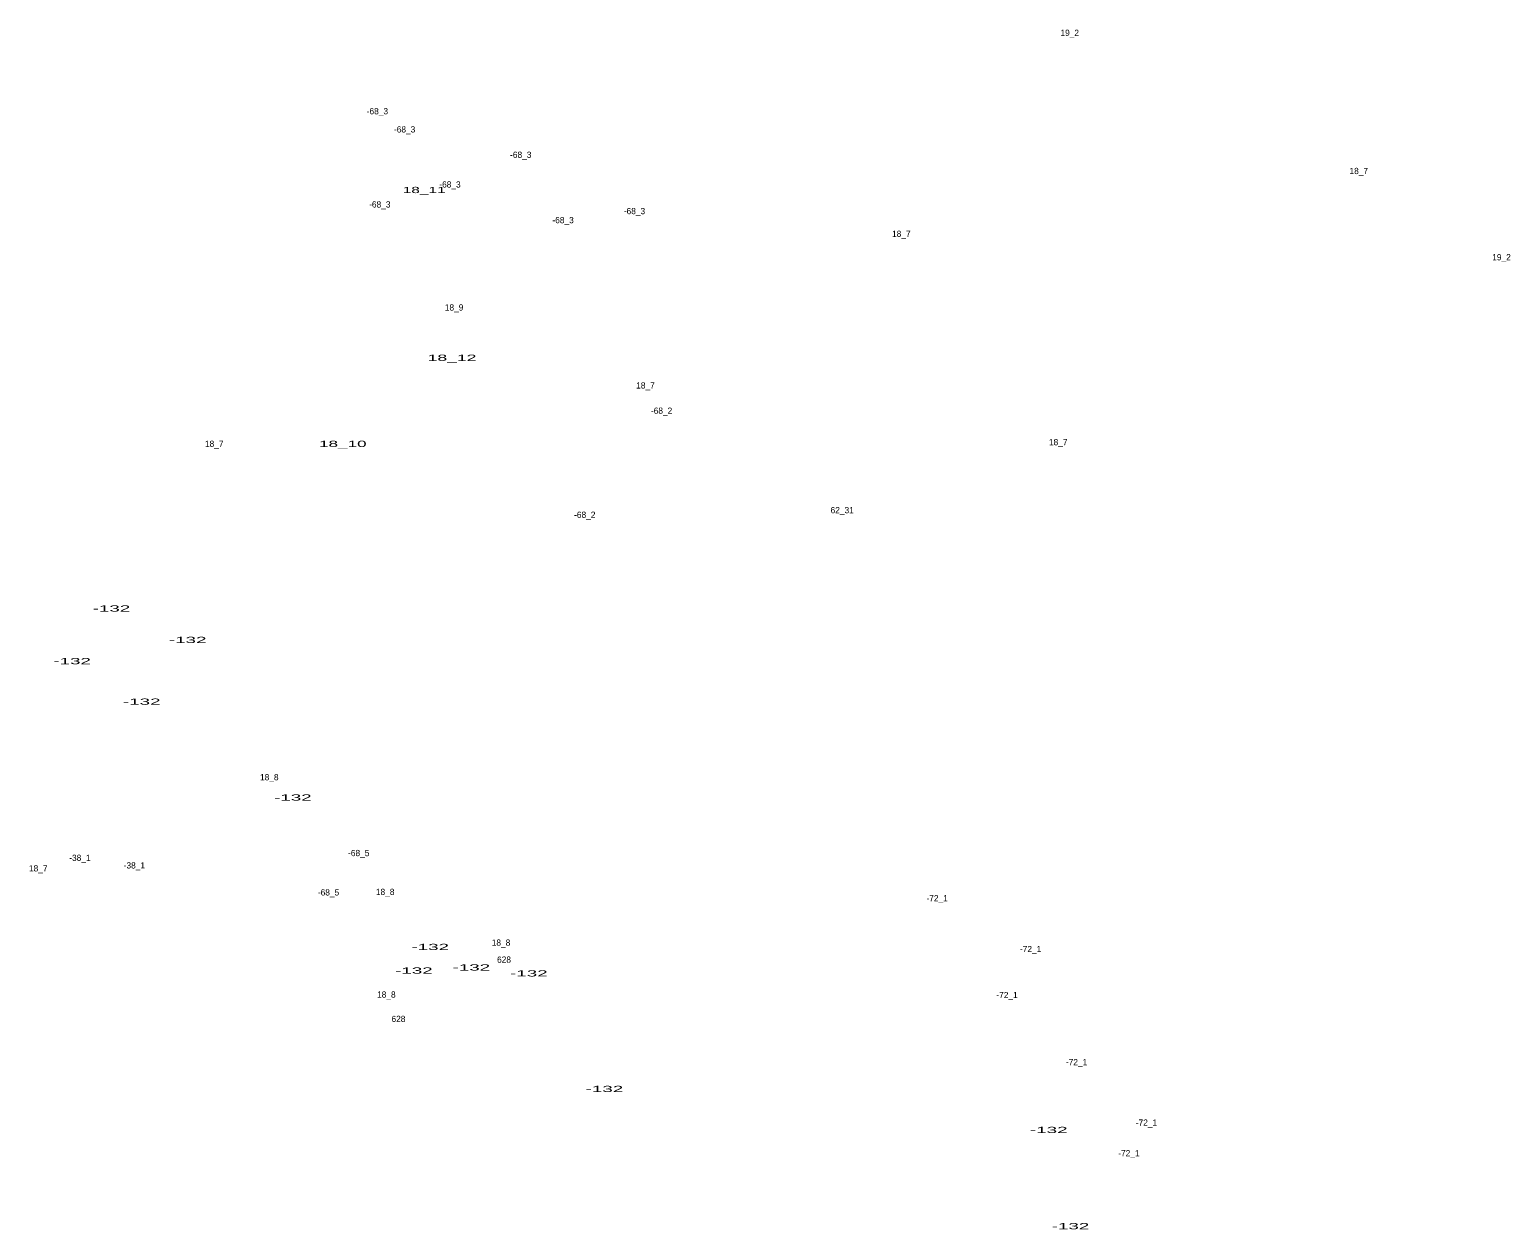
# Model space of a CAD drawing. Extents: x -661742 to -657295, y -1002932 to -996888.
# Drawn here: x -660423 to -659474, y -1002932 to -1002163 of the extents above; entities that cross this region are included whole.
import ezdxf
from ezdxf.enums import TextEntityAlignment as Align

# ---------------------------------------------------------------- set-up
doc = ezdxf.new("R2010")
doc.units = 0
doc.header["$LTSCALE"] = 1.6
doc.layers.add('24', color=7, linetype='Continuous')

msp = doc.modelspace()

# ---------------------------------------------------------------- texts
at = {"layer": '24'}
for s, p in [('19_2', (-659756.664, -1002167.17)), ('-68_3', (-660200.438, -1002217.4)), ('-68_3', (-660182.988, -1002229.04)), ('-68_3', (-660108.538, -1002245.33)), ('18_7', (-659571.404, -1002255.71)), ('-68_3', (-660153.908, -1002264.33)), ('-68_3', (-660198.888, -1002277.13)), ('-68_3', (-660081.398, -1002287.22)), ('-68_3', (-660035.648, -1002281.4)), ('18_7', (-659864.604, -1002295.96)), ('19_2', (-659479.904, -1002310.97)), ('18_9', (-660151.264, -1002343.19)), ('18_7', (-660028.604, -1002393.13)), ('-68_2', (-660018.268, -1002409.35)), ('18_7', (-659764.034, -1002429.5)), ('18_7', (-660305.014, -1002430.55)), ('-68_2', (-660067.508, -1002476.06)), ('62_31', (-659902.514, -1002473.08)), ('18_8', (-660269.719, -1002644.25)), ('-68_5', (-660212.378, -1002692.86)), ('18_7', (-660417.804, -1002702.65)), ('-38_1', (-660391.106, -1002695.91)), ('-38_1', (-660356.206, -1002700.76)), ('-68_5', (-660231.758, -1002718.07)), ('18_8', (-660195.449, -1002717.77)), ('-72_1', (-659841.642, -1002721.8)), ('18_8', (-660121.189, -1002750.28)), ('628', (-660119.273, -1002761.18)), ('-72_1', (-659781.732, -1002754.39)), ('18_8', (-660194.679, -1002783.55)), ('-72_1', (-659796.862, -1002783.87)), ('628', (-660186.933, -1002799.19)), ('-72_1', (-659752.272, -1002826.85)), ('-72_1', (-659707.482, -1002865.64)), ('-72_1', (-659718.732, -1002885.23))]:
    msp.add_text(s, height=4, dxfattribs=at).set_placement(p, align=Align.CENTER)
for s, width, p in [('18_11', 1.85, (-660170.461, -1002267.89)), ('18_12', 2.1, (-660152.575, -1002375.42)), ('18_10', 2.05, (-660222.601, -1002430.61)), ('-132', 2.25, (-660370.881, -1002536.1)), ('-132', 2.25, (-660322.031, -1002556.27)), ('-132', 2.25, (-660396.091, -1002569.84)), ('-132', 2.25, (-660351.501, -1002595.83)), ('-132', 2.25, (-660254.591, -1002657.25)), ('-132', 2.25, (-660166.571, -1002753.05)), ('-132', 2.25, (-660177.041, -1002768.18)), ('-132', 2.25, (-660140.211, -1002766.17)), ('-132', 2.25, (-660103.371, -1002769.98)), ('-132', 2.25, (-660054.911, -1002844.06)), ('-132', 2.25, (-659770.111, -1002870.34)), ('-132', 2.25, (-659756.161, -1002932.01))]:
    msp.add_text(s, height=4, dxfattribs=dict(at, width=width)).set_placement(p, align=Align.CENTER)

doc.saveas('drawing.dxf')
